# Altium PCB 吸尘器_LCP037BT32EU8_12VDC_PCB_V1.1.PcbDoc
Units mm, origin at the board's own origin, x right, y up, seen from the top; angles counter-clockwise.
Board outline 41.5 x 41.5 mm, 2 copper layers (Top Layer, Bottom Layer); 77 components, 42 nets, 206 pads, 122 vias.
Unrouted connection lines stored in the file: 7.
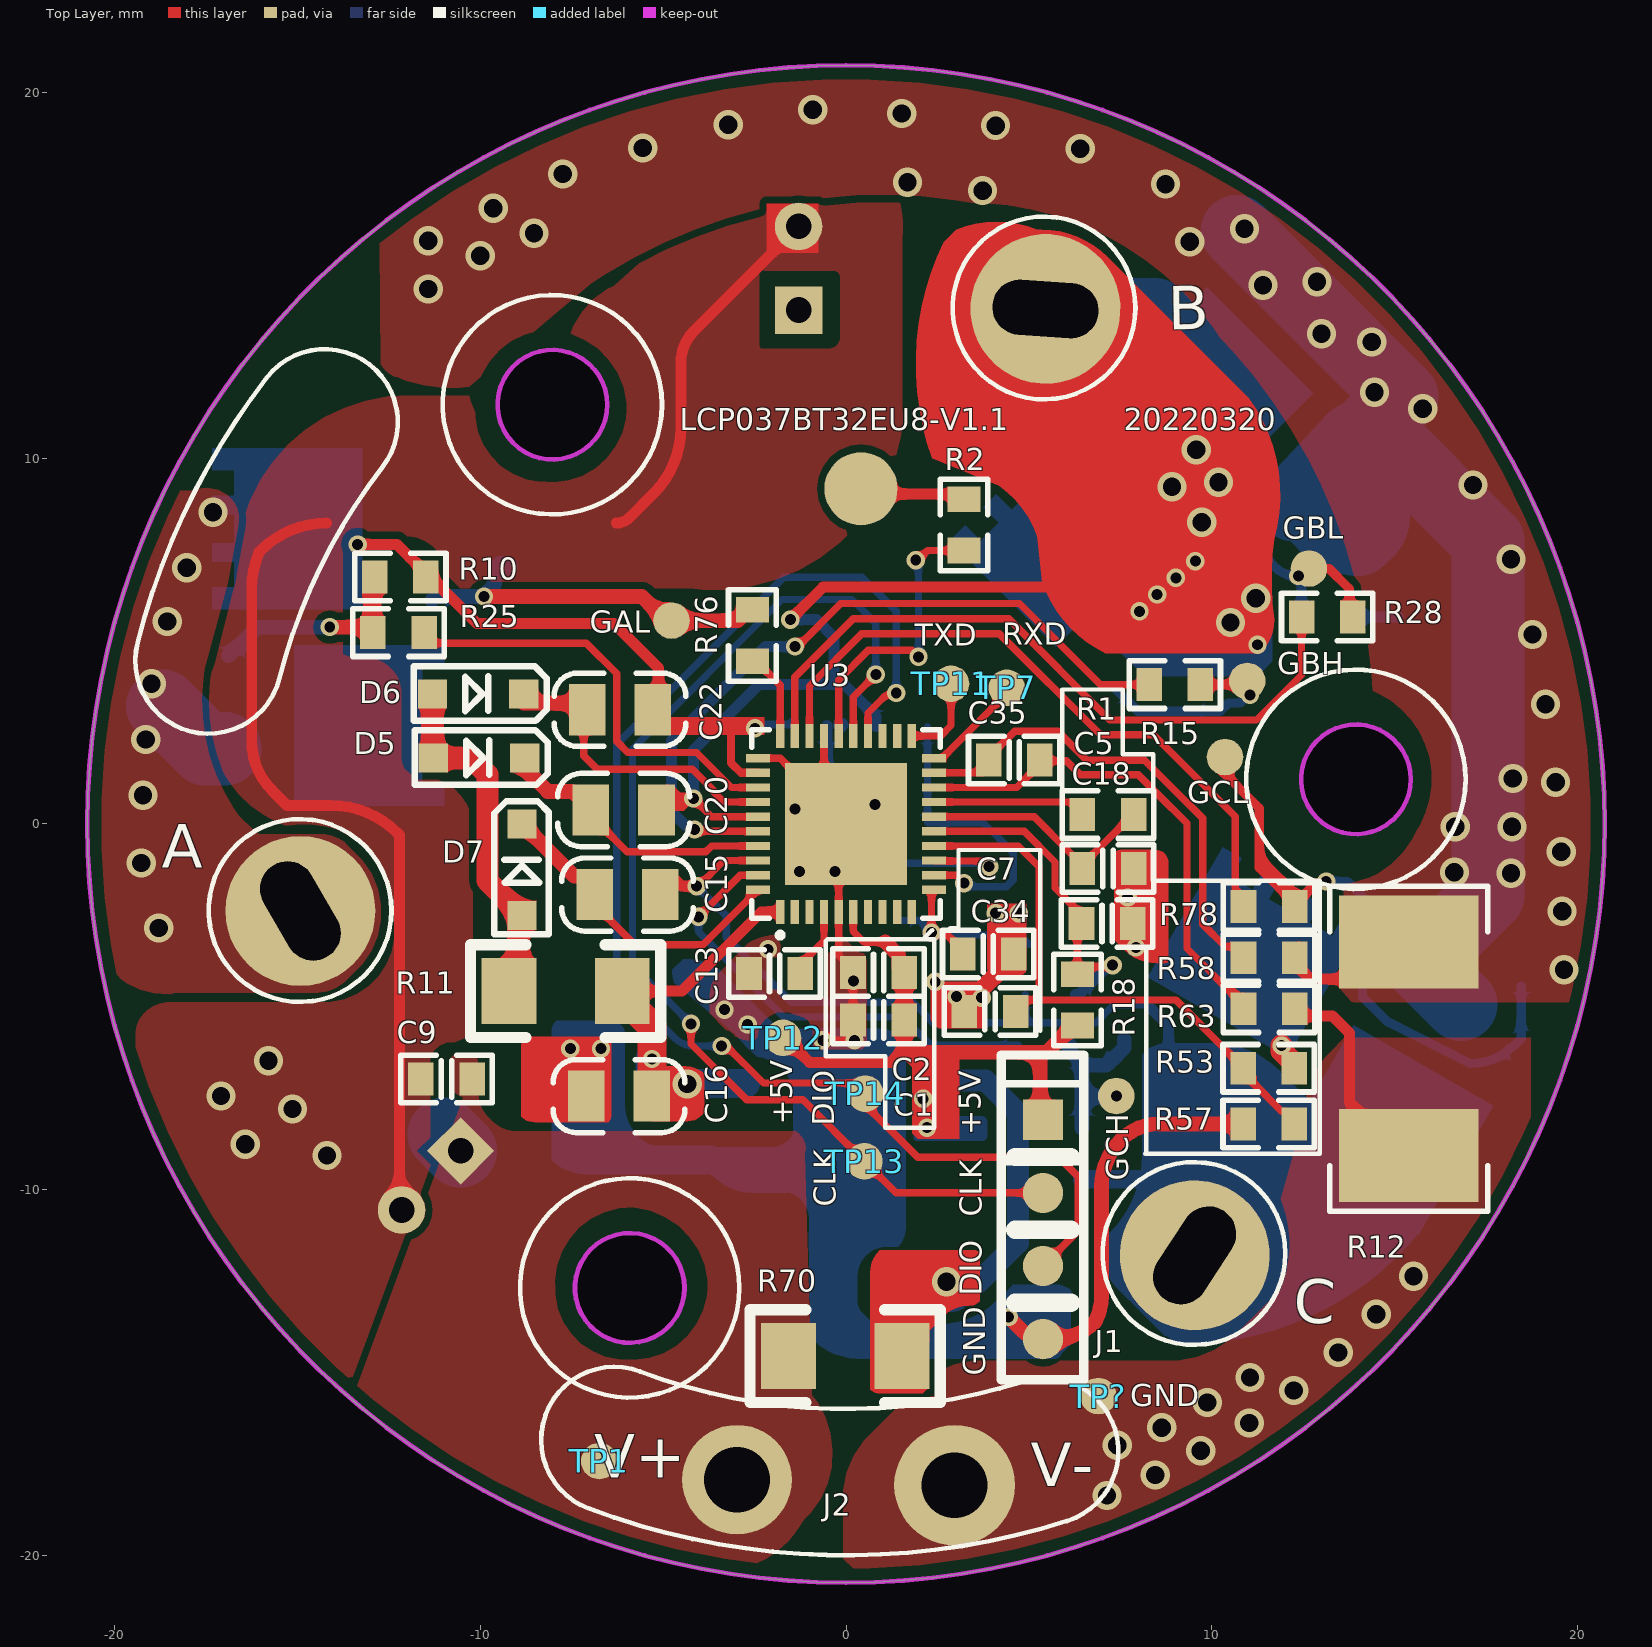
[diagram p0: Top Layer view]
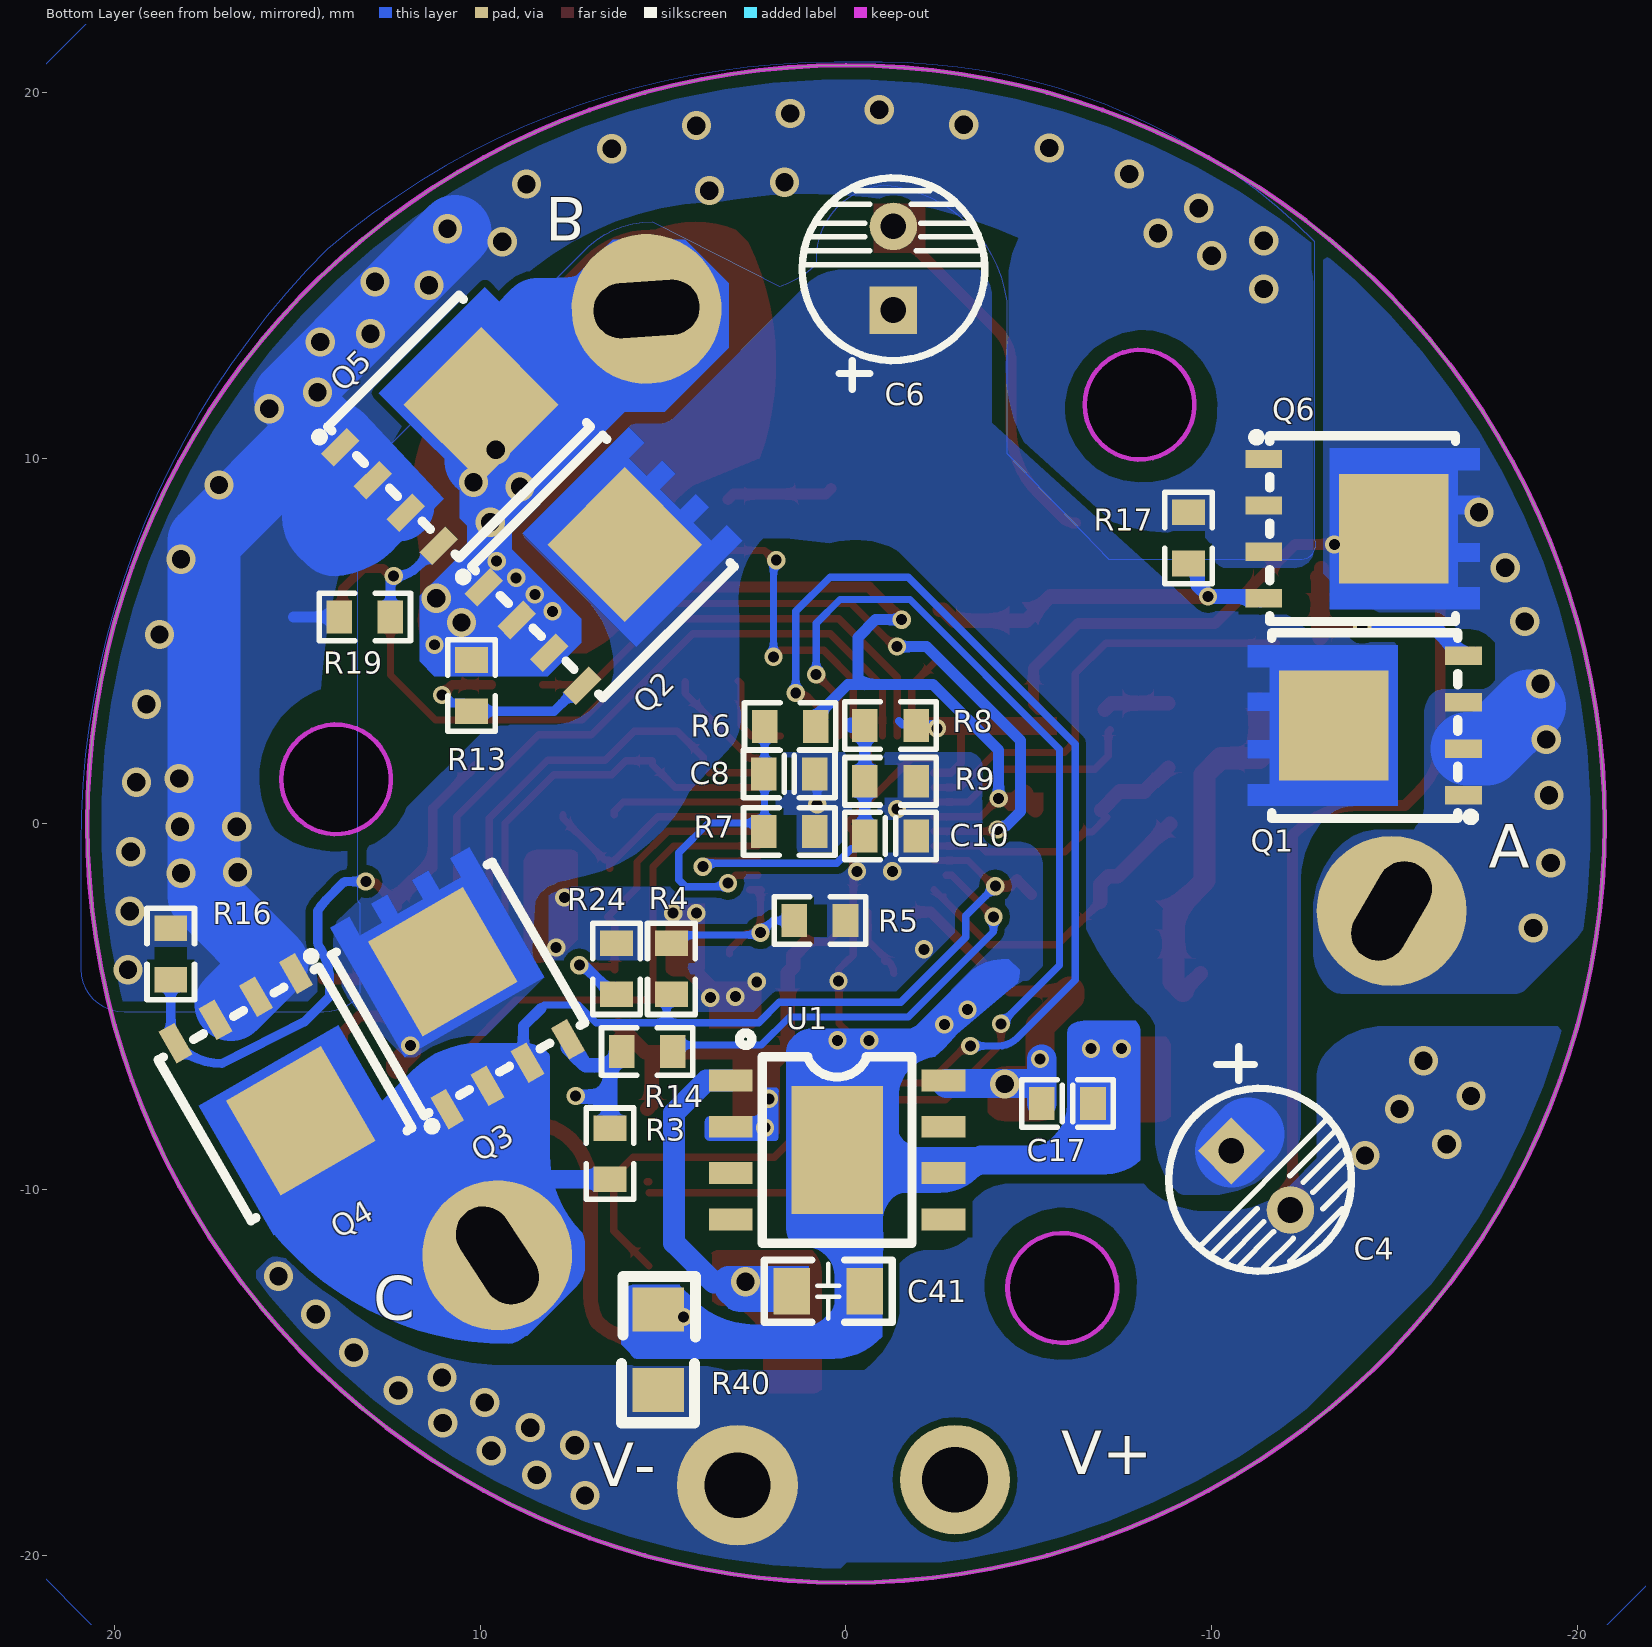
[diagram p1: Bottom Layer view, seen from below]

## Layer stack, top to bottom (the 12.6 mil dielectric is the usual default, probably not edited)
Top Solder: solder mask 0.0102, Solder Resist, Dk 3.5
Top Layer: signal copper 0.0356
Dielectric1: dielectric 0.32, FR-4, Dk 4.8
Bottom Layer: signal copper 0.0356
Bottom Solder: solder mask 0.0102, Solder Resist, Dk 3.5

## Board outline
-20.753,-0.001 ccw(c-0.003,-0.001) -0.003,-20.751 ccw(c-0.003,-0.001) 20.747,-0.001 ccw(c-0.003,-0.001) -0.003,20.749 ccw(c-0.003,-0.001)
cut-out: -7.418,-12.689 ccw(c-5.918,-12.689) -5.918,-14.189 ccw(c-5.918,-12.689) -4.418,-12.689 ccw(c-5.918,-12.689) -5.918,-11.189 ccw(c-5.918,-12.689)
cut-out: 12.444,1.221 ccw(c13.944,1.221) 13.944,-0.279 ccw(c13.944,1.221) 15.444,1.221 ccw(c13.944,1.221) 13.944,2.721 ccw(c13.944,1.221)
cut-out: -9.534,11.467 ccw(c-8.034,11.467) -8.034,9.967 ccw(c-8.034,11.467) -6.534,11.467 ccw(c-8.034,11.467) -8.034,12.967 ccw(c-8.034,11.467)

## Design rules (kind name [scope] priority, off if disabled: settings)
BoardOutlineClearance [All] p1: gap=0.381
Clearance [All] p1: gap=0.2
ComponentClearance [All] p1: gap=0 collisioncheckmode=3 verticalgap=0 showdistances=FALSE
HoleSize [All] p1: absolutevalues=TRUE maxlimit=4 minlimit=0.025 maxpercent=80.000 minpercent=20.000
MinimumSolderMaskSliver [All] p1: minsoldermaskwidth=0.18
PlaneConnect [All] p1: planeconnectstyle=Direct reliefexpansion=0.508 reliefentries=4 reliefconductorwidth=0.254 reliefairgap=0.254
PolygonConnect [All] p1: connectstyle=Direct reliefconductorwidth=0.254 reliefentries=4 polygonreliefangle="90 Angle" airgapwidth=0.254
RoutingVias [All] p1: holewidth=0.3 width=0.5 viastyle="Through Hole" minholewidth=0.2 minwidth=0.4 maxholewidth=0.3 maxwidth=0.5
SolderMaskExpansion [All] p1: expansion=0.102
Width [All] p1: maxlimit=5 minlimit=0.2 preferedwidth=0.254
26 further rules are at their usual default settings.

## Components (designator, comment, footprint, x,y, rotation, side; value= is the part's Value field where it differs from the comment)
A "Wire#18(BL)6cm" TP4MM#1 -10.825,-2.3 r270 top locked
B "Wire#18-(WT)6cm" TP4MM#2 0.85,14.075 r91 top locked
C "Wire#18(YE)6cm" TP4MM#3 15.925,-16.55 r177 top locked
C1 "106/25V" C0603X 0.889,-5.359 r180 top
C2 "0.1uF/50V" C0603X 0.889,-4.064 r0 top
C4 "100uF/35V" CDE5*7 -11.35,-9.75 r225 bottom
C5 "Cap" C0603X 7.163,-1.219 r0 top
C6 "100uF/35V" CDE5*7 -1.3,15.2 r90 bottom locked
C7 "332/50V" C0603X 3.886,-3.556 r0 top
C8 "332/50V" C0603X 1.549,1.372 r180 bottom
C9 "104/50V" C0603X -10.928,-6.977 r0 top
C10 "332/50V" C0603X -1.219,-0.33 r180 bottom
C13 "0.1uF/50V 0603" C0603X -1.956,-4.089 r180 top
C15 "10uF/25V 0805" C0805 -5.08,-1.93 r180 top
C16 "10uF/25V 0805" C0805 -7.112,-7.442 r0 top
C17 "0.1uF/50V 0603" C0603X -6.059,-7.645 r180 bottom
C18 "103/50V 0603" C0603X 7.137,-2.718 r0 top
C20 "10uF/25V 0805" C0805 -5.185,0.381 r180 top
C22 "10uF/25V 0805" C0805 -5.283,3.124 r180 top
C34 "104/50V" C0603X 3.937,-5.131 r0 top
C35 "101/50V" C0603X 4.597,1.753 r0 top
C41 "10uF/25V" 0805C 0.483,-12.776 r0 bottom
D5 "SD103AW" SOD323 -11.288,1.803 r0 top
D6 "SD103AW" SOD323 -11.314,3.556 r0 top
D7 "SD103AW" SOD323 -8.865,-2.5 r90 top
GAL "TestPoint" TP_1.0-A -4.775,5.563 r180 top (schematic designator TP8)
GBH "TestPoint" TP_1.0-A 10.973,3.912 r90 top (schematic designator TP5)
GBL "TestPoint" TP_1.0-A 12.66,6.985 r90 top (schematic designator TP9)
GCH "TestPoint" TP_1.0-A 7.391,-7.442 r90 top (schematic designator TP6)
GCL "TestPoint" TP_1.0-A 10.363,1.829 r90 top (schematic designator TP10)
J1 "CON4" SIP-4-TP 5.385,-8.09 r270 bottom locked
J2 "CON2" CON2-1.7MM -0.533,-18.11 r180 top
Q1 "1511" DNF5*6 -16.891,0.787 r90 bottom locked
Q2 "1511" DNF5*6 9.906,6.477 r225 bottom locked
Q3 "1511" DNF5*6 10.904,-7.798 r150 bottom locked
Q4 "1511" DNF5*6 15.039,-4.089 r330 bottom locked
Q5 "1511" DNF5*6 13.836,10.305 r225 bottom locked
Q6 "1511" DNF5*6 -11.43,9.982 r270 bottom locked
R1 "10K" R0603X 7.163,0.254 r0 top
R2 "1K" R0603X 3.226,8.179 r90 top
R3 "20K" R0603X 6.452,-9.017 r270 bottom
R4 "22K 1%" R0603X 4.775,-3.962 r90 bottom
R5 "5.1K 1%" R0603X 0.711,-2.642 r180 bottom
R6 "22K 1%" R0603X 1.524,2.667 r0 bottom
R7 "5.1K 1%" R0603X 1.549,-0.203 r180 bottom
R8 "22K 1%" R0603X -1.219,2.692 r0 bottom
R9 "5.1K 1%" R0603X -1.219,1.168 r180 bottom
R10 "20K" R0603X -12.192,6.756 r0 top
R11 "5.1R/1206" 1206/X -7.671,-4.572 r0 top
R12 "5mR/2512" 2512A 15.392,-3.353 r270 top
R13 "20K" R0603X 10.236,3.785 r90 bottom
R14 "51R 5% 0603" R0603X 5.436,-6.223 r180 bottom
R15 "51R 5% 0603" R0603X 8.992,3.81 r180 top
R16 "20K" R0603X 18.466,-3.556 r90 bottom
R17 "20K" R0603X -9.373,7.823 r90 bottom
R18 "5.1K 1% 0603" R0603X 6.325,-4.812 r90 top
R19 "20K" R0603X 13.157,5.664 r0 bottom
R24 "10K NTC B=4250" R0603X 6.274,-3.962 r270 bottom
R25 "51R 5% 0603" R0603X -12.243,5.232 r0 top
R28 "51R 5% 0603" R0603X 13.157,5.664 r180 top
R40 "0R 0805" R0805 5.131,-14.376 r270 bottom
R53 "100K 1% 0603" R0603X 11.557,-6.68 r0 top
R57 "10K 1% 0603" R0603X 11.557,-8.204 r0 top
R58 "68R 1% 0603" R0603X 11.568,-3.658 r0 top
R63 "68R 1% 0603" R0603X 11.568,-5.055 r0 top
R70 "20R 5% 1206" 1206/X -0.025,-14.554 r0 top
R76 "51R 5% 0603" R0603X -2.565,5.156 r270 top
R78 "51R 5% 0603" R0603X 11.568,-2.261 r180 top
TP1 "TestPoint" TP_1.0-A -6.75,-17.425 r90 top
TP7 "TestPoint" TP_1.0-A 4.394,3.727 r90 top
TP11 "TestPoint" TP_1.0-A 2.87,3.835 r90 top
TP12 "TestPoint" TP_1.0-A -1.725,-5.85 r90 top locked
TP13 "TestPoint" TP_1.0-A 0.5,-9.225 r90 top locked
TP14 "TestPoint" TP_1.0-A 0.525,-7.375 r90 top locked
TP? "TestPoint" TP_1.0-A 6.9,-15.648 r90 top locked
U1 "EG1205" ESOP-8 0.241,-8.915 r270 bottom locked
U3 "LCP037B32B" QFN-40-1 -0.503,-0.526 r0 top locked

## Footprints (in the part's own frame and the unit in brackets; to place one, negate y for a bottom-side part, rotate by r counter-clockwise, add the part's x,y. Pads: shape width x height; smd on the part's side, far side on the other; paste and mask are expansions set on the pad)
0805C [mm]
  rect 1x1.27 smd: 1(-1,0) 2(1,0)
  silkscreen extent -1.75,-0.85 1.75,0.85
1206/X [mm]
  rect 1.5x1.8 smd: 1(-1.55,0) 2(1.55,0)
  silkscreen extent -2.6,-1.27 2.6,1.27
2512A [mil]
  rect 100x150 smd: 1(-5,0) 2(225,0)
  silkscreen extent -65,-85 285,85, body extent -17,-66 243,66, height 33
C0603X [mm]
  rect 0.7x0.9 smd: 1(-0.7,0) 2(0.7,0)
  Top Layer pour cut-out: -0.2,0.45 -0.2,-0.45 0.2,-0.45 0.2,0.45
  silkscreen extent -1.25,-0.65 1.25,0.65
C0805 [mm]
  rect 1x1.4 smd: 1(0,0) 2(1.8,0)
  silkscreen extent -0.9,-1 2.7,1
CDE5*7 [mm]
  rect 1.3x1.3 hole 0.7: 1(-1.143,0)
  round 1.3 hole 0.7: 2(1.143,0)
  silkscreen extent -2.53,-2.5 2.47,2.5, body extent -2.5,-2.5 2.5,2.5, height 7
CON2-1.7MM [mm]
  round 3.3 hole 1.8: 1(-3.5,-0.025)
  round 3 hole 1.8: 2(2.45,-0.175)
DNF5*6 [mm]
  rect 0.5x1 smd: 1(0,0) 1(1.27,0) 1(2.54,0) 4(3.81,0)
  rect 3x3 smd: 5(1.905,3.55)
  Top Layer region: -0.295,1.8 -0.295,5.9 0.305,5.9 0.305,5.3 1.005,5.3 1.005,5.9 1.505,5.9 1.505,5.3 2.305,5.3 2.305,5.9 2.805,5.9 2.805,5.3 3.505,5.3 3.505,5.9 4.105,5.9 4.105,1.8
  silkscreen extent -0.69,-0.3 4.45,5.24
ESOP-8 [mm] "EG1205"
  rect 0.6x1.2 smd: 1(-1.905,-2.908) 2(-0.635,-2.908) 3(0.635,-2.908) 4(1.905,-2.908) 5(1.905,2.908) 6(0.635,2.908) 7(-0.635,2.908) 8(-1.905,2.908)
  rect 3.5x2.5 smd: 9(0,0)
  silkscreen extent -3.2,-2.67 2.55,2.05
QFN-40-1 [mm]
  rect 0.224x0.665 smd: 1(-1.3,-1.882) 2(-0.9,-1.882) 3(-0.5,-1.882) 4(-0.1,-1.882) 5(0.3,-1.882) 6(0.7,-1.882) 7(1.1,-1.882) 8(1.5,-1.882) 9(1.9,-1.882) 10(2.3,-1.882) 21(2.3,2.933) 22(1.9,2.933) 23(1.5,2.933) 24(1.1,2.933) 25(0.7,2.933) 26(0.3,2.933) 27(-0.1,2.933) 28(-0.5,2.933) 29(-0.9,2.933) 30(-1.3,2.933)
  rect 0.665x0.224 smd: 11(2.907,-1.275) 12(2.907,-0.875) 13(2.907,-0.475) 14(2.907,-0.075) 15(2.907,0.325) 16(2.907,0.725) 17(2.907,1.125) 18(2.907,1.525) 19(2.907,1.925) 20(2.907,2.325) 31(-1.908,2.325) 32(-1.908,1.925) 33(-1.908,1.525) 34(-1.908,1.125) 35(-1.908,0.725) 36(-1.908,0.325) 37(-1.908,-0.075) 38(-1.908,-0.475) 39(-1.908,-0.875) 40(-1.908,-1.275)
  rect 3.325x3.325 smd: 41(0.5,0.525)
  silkscreen extent -2.08,-2.59 3.08,3.1
R0603X [mm]
  rect 0.7x0.9 smd: 1(-0.7,0) 2(0.7,0)
  Top Layer pour cut-out: -0.2,0.45 -0.2,-0.45 0.2,-0.45 0.2,0.45
  silkscreen extent -1.25,-0.65 1.25,0.65
R0805 [mm]
  rect 1.2x1.4 smd: 1(-1.1,0) 2(1.1,0)
  silkscreen extent -2,-1.01 2,1.02
SIP-4-TP [mm] "贴片针座"
  rect 1.1x1.1 smd far side: 1(0,0)
  round 1.1 smd far side: 2(2,0) 3(4,0) 4(6,0)
SOD323 [mm]
  rect 0.8x0.8 smd: 1(0,0) 2(2.5,0)
  silkscreen extent -0.51,-0.74 3.12,0.76, body extent -0.06,-0.64 2.54,0.66, height 1
TP4MM#1 [mm] "LX-椭圆插件"
  round 4.1 hole 1.5 slot 2.9 at 30 deg: 1(0.079,-4.1)
TP4MM#2 [mm] "LX-椭圆插件"
  round 4.1 hole 1.5 slot 2.9 at 85 deg: 1(-0.069,-4.602)
TP4MM#3 [mm] "LX-椭圆插件"
  round 4.1 hole 1.5 slot 2.9 at 60 deg: 1(6.632,-4.409)
TP_1.0-A [mm] "无丝印"
  round 1 smd: 1(0,0)

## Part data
A B C: library part Wire
C1 C9 C15 C16 C20 C22 C34 C35 C41: library part CAP, "Capacitor"
C2 C7 C8 C10 C13 C17 C18: library part CAP
C4 C6: library part ELECTRO1, "Electrolytic Capacitor"
C5: "Capacitor"
D5 D6 D7: library part DIODE, "SBD"
GAL GBH GBL GCH GCL TP1 TP7 TP11 TP12 TP13 TP14 TP?: "Testpoint"
J2: "Connector"
Q1 Q2 Q3 Q4 Q5 Q6: library part RJK0822, "NMOS"
R1 R2: library part R
R3 R4 R5 R6 R7 R8 R9 R10 R11 R13 R16 R17 R19: library part RES2
R12 R14 R15 R25 R28 R76 R78: library part Res2, "Resistor"
R18 R40 R53 R57 R58 R63 R70: library part RES
R24: library part RES-V
U3: library part LCP037B32A

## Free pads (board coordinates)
  round 2 smd: 10(0.406,9.169)

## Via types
v1: diameter 0.8, hole 0.5, Top Layer to Bottom Layer, tented both sides, 69 vias
v2: diameter 0.5, hole 0.3, Top Layer to Bottom Layer, tented both sides, 53 vias

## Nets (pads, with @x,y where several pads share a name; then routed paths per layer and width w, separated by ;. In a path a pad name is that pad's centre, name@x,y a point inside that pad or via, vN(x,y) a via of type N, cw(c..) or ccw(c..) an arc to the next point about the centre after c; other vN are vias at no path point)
+5V: C1.1 C2.2 J1.1 R18.1 TP12.1 U1.2 U3.6 | length 18.1
  Top Layer w0.2: U3.6 0.197,-2.896 ccw(c0.304,-2.896) 0.229,-2.972 0.483,-3.226 1.067,-3.226
  Top Layer w0.3: TP12.1 -1.668,-5.85 -1,-6.518 1.229,-6.518 1.499,-6.248
  Top Layer w0.4: 1.067,-3.226 1.439,-3.598 1.439,-3.914 C2.2 C1.1 1.589,-6.158 1.499,-6.248 2.057,-6.248 ; v2(2.21,-8.306) 2.21,-6.401 2.057,-6.248 ; J1.1@5.436,-7.786 5.309,-7.659 5.309,-6.248 ; R18.1@6.225,-5.512 5.488,-6.248 5.309,-6.248 ; 2.057,-6.248 5.309,-6.248
  Bottom Layer w0.3: v2(2.21,-8.306) 2.222,-8.293 3.137,-8.293 U1.2
  other v2: 2.108,-7.518
+12V: C16.2 C17.1 R11.2 U1.8 U3.1 | length 12.2
  Top Layer w0.3: R11.2 -4.484,-4.572 -2.32,-2.408 U3.1@-1.865,-2.408
  Top Layer w0.8: R11.2 -6.121,-4.722 -5.309,-5.534 v2(-5.309,-6.426) ; C16.2 v2@-5.312,-6.426
  Bottom Layer w0.8: C17.1 -5.359,-7.01 ; v2@-5.359,-6.426 -5.359,-7.01 ; U1.8@-2.755,-7.098 -5.271,-7.098 -5.359,-7.01
  other v1: -4.343,-7.112
DCIN: C4.1 C6.1 C9.2 J2.2 Q1.5 Q2.5 Q3.5 R53.2 R70.1 TP1.1 | length 1.4
  Top Layer w0.6: v2(11.913,-6.064) 11.913,-6.21 12.282,-6.58 R53.2@12.282,-6.68
  Bottom Layer w2: C4.1@-10.998,-8.485 C4.1
GAH: Q1.4 R10.1 R25.1 | length 7.6
  Top Layer w0.4: v2(-14.122,5.385) -13.235,5.385 R25.1@-13.159,5.461 ; R25.1@-13.006,5.232 R10.1@-13.006,6.998 ; R25.1@-12.968,5.08 -13.006,5.118 -12.917,5.207 -12.917,6.731 R10.1
  Bottom Layer w0.4: Q1.4 -16.104,5.385 v2(-14.122,5.385)
GAL: GAL.1 Q6.4 R17.1 R76.1 | length 10.5
  Top Layer w0.4: v2(-9.906,6.223) -5.588,6.223 -4.928,5.563 GAL.1 -2.959,5.563 -2.665,5.856 R76.1
  Bottom Layer w0.4: Q6.4@-11.328,6.121 -11.227,6.223 v2(-9.906,6.223) -9.906,6.25 -9.623,6.533 -9.623,6.973 -9.473,7.123 R17.1 ; R17.1@-9.276,6.993 R17.1@-9.169,7.072
GBH: GBH.1 Q2.4 R13.1 R15.1 | length 5.8
  Top Layer w0.254: R15.1 10.77,3.81 v2(11.049,3.531)
  Bottom Layer w0.254: Q2.4 7.283,3.783 7.981,3.085 R13.1 10.459,3.308 10.777,3.308 11,3.531 v2(11.049,3.531)
GBL: GBL.1 Q5.4 R19.1 R28.1 | length 5.3
  Top Layer w0.254: GBL.1@12.344,6.843 ccw(c12.431,6.843) v2(12.37,6.782) ccw(c12.431,6.843) 12.431,6.756 GBL.1 13.208,6.985 13.749,6.444 cw(c13.705,6.401) 13.767,6.401 13.767,5.882 ccw(c14.075,5.882) R28.1
  Bottom Layer w0.254: Q5.4 11.711,7.042 ccw(c12.392,7.723) 12.392,6.759 cw(c12.235,6.602) 12.457,6.602 R19.1
GCH: GCH.1 Q3.4 R3.1 R14.1 | length 5
  Bottom Layer w0.4: R14.1@6.11,-6.223 R14.1@6.11,-6.045 ; R14.1 6.452,-6.539 R14.1@6.452,-6.604 ; R14.1@6.364,-6.604 R14.1@6.452,-6.604 ; R3.1 6.452,-7.461 ; v2(7.391,-7.442) 7.372,-7.461 6.452,-7.461 ; Q3.4 7.605,-6.117 7.118,-6.604 R14.1@6.452,-6.604 ; 6.452,-7.461 R14.1@6.452,-6.604
GCL: GCL.1 Q4.4 R16.1 R78.1 | length 17.9
  Top Layer w0.254: GCL.1@10.135,1.6 11.303,0.432 11.303,-0.927 ; R78.1 12.268,-2.161 11.303,-1.195 11.303,-0.927 ; v2(13.132,-1.575) 13.085,-1.622 12.856,-1.622 12.427,-2.051 11.303,-0.927
  Bottom Layer w0.254: v2(13.132,-1.575) 13.665,-1.575 cw(c13.665,-1.697) 13.752,-1.611 14.224,-2.083 cw(c13.246,-3.061) 14.448,-2.376 14.448,-3.196 cw(c14.118,-3.196) 14.423,-3.321 cw(c14.118,-3.196) 14.361,-3.418 ccw(c15.852,-4.295) 14.122,-4.295 14.122,-4.724 14.808,-5.41 17.069,-6.553 ccw(c17.069,-4.836) 18.283,-6.05 Q4.4 18.466,-5.867 R16.1@18.466,-4.434
GND: C1.2 C2.1 C5.2 C7.2 C8.2 C10.2 C13.2 C16.1 C17.2 C18.2 C34.1 C41.1 J1.4 R5.2 R7.2 R9.2 R24.1 R40.1 R57.1 U1.6 U1.9 U3.5 U3.27 U3.31 U3.41 | length 42.9
  Top Layer w0.2: U3.31 -1.803,1.799 U3.41@-0.603,0.599 ; U3.27 U3.41@-0.603,0.599 ; v2@-0.515,-5.773 -0.37,-5.918 v2(0.229,-5.918) ; C1.2@-0.061,-5.709 0.189,-5.459 C1.2 C2.1 0.203,-4.078 v2(0.203,-4.293) 0.203,-3.978 -0.061,-3.714 -0.086,-3.714 -0.203,-3.597 U3.5 -0.203,-0.201 U3.41 U3.41@-0.603,0.599 ; C34.1 3.237,-5.031 v2@3.613,-4.655 ; C7.2@4.336,-3.932 4.336,-3.806 C7.2 4.586,-3.353 C7.2@4.724,-3.215
  Top Layer w0.3: C5.2@7.888,-1.041 7.901,-1.054 7.901,-2.629 7.919,-2.647 7.919,-3.373 v2(7.925,-3.378)
  Top Layer w0.4: v2@3.613,-4.655 C7.2@4.336,-3.932 ; v2(4.445,-13.487) 4.81,-13.852 ccw(c5.385,-13.277) J1.4 5.661,-14.09 ccw(c5.661,-12.466) 6.227,-13.988 ccw(c5.661,-12.466) 6.81,-13.614 ccw(c5.448,-12.902) 6.985,-12.902 6.985,-9.924 cw(c8.806,-9.924) 7.518,-8.636 cw(c8.561,-9.678) 8.561,-8.204 R57.1
  Bottom Layer w0.2: v2(0.787,0.533) 0.787,1.23 0.889,1.332 C8.2
  Bottom Layer w0.5: C17.2 -6.759,-7.745 -6.709,-7.795 -6.659,-7.845 -6.659,-8.403 -6.02,-9.042 -3.683,-9.042 -3.175,-9.55 U1.6
  Bottom Layer w0.6: C17.2 -6.709,-7.695 -6.709,-7.795 -6.709,-8.353 -6.659,-8.403
  Bottom Layer w1: U1.6 U1.9@-0.394,-9.55 ; C41.1@-0.382,-12.911 -0.517,-12.911 C41.1 -0.517,-10.174 -0.394,-10.051 U1.9@-0.394,-9.55 ; U1.9 U1.9@-0.394,-9.55 ; v2(4.445,-13.487) R40.1
  other v2: -7.544,-6.147 -6.706,-6.147 -0.635,-5.918 -2.692,-5.486 -3.327,-5.08 3.708,-4.75 3.023,-4.724 2.438,-4.318 -2.134,-3.429 4.089,-2.438 4.724,-2.438 7.702,-2.012 -1.27,-1.295 -0.305,-1.295 -1.397,0.406
IN: C41.2 R70.2 U1.1 | length 12.5
  Top Layer w0.6: R70.2 1.975,-14.104 1.975,-12.707 2.134,-12.548 3.277,-12.548
  Bottom Layer w0.6: C41.2@1.483,-12.548 3.607,-12.548 4.699,-11.455 4.699,-7.899 3.81,-7.01 U1.1
  other v1: 2.743,-12.522
ISENCE: Q4.1 Q5.1 Q6.1 R12.1 R16.2 R17.2 R19.2 R58.2 | length 33.1
  Top Layer w0.3: R58.2@12.384,-3.353 12.384,-3.926 12.7,-4.242 R12.1@14.3,-4.242
  Bottom Layer w0.3: R19.2 15.113,5.664 ; 13.857,7.152 13.97,7.264
  Bottom Layer w2: v1@10.689,16.2 12.467,14.423 15.197,11.692 14.14,10.635 14.14,10.61 ; 12.256,8.725 14.14,10.61 ; 16.816,-4.936 15.693,-3.814 17.412,-2.095 17.551,-1.956 17.551,-0.076 17.551,7.74 14.682,10.61 14.14,10.61
  other v1: 19.634,-3.988 19.583,-2.388 18.186,-1.346 16.637,-1.321 19.558,-0.762 16.662,-0.076 18.212,-0.076 19.406,1.143 18.237,1.245 19.126,3.277 18.771,5.182 18.186,7.239 17.145,9.271 15.773,11.354 14.453,11.811 14.376,13.183 13.005,13.411 -11.43,14.63 11.405,14.732 12.878,14.834 -10.008,15.545 9.398,15.926 -11.43,15.951 -8.534,16.154 10.897,16.281 -9.652,16.84 3.734,17.323 8.738,17.501 1.676,17.551 -7.747,17.78 6.401,18.466 -5.563,18.491 4.089,19.101 -3.226,19.126 1.524,19.431 -0.914,19.533
MosTemp: C18.1 R18.2 R24.2 U3.15 | length 9.4
  Top Layer w0.2: U3.15 4.874,-0.201 5.715,-1.041 5.715,-1.743 6.514,-2.542 6.325,-2.731 6.325,-3.993 6.415,-3.903 7.248,-3.903 v2(7.29,-3.861)
  Bottom Layer w0.2: v2@7.232,-3.918 v2(7.29,-3.861)
  Bottom Layer w0.3: R24.2 6.374,-4.662 7.137,-3.899 7.213,-3.899 v2@7.232,-3.918
MOTOR_A: A.1 C22.1 Q1.1 Q6.5 R8.1 R10.2 U3.32 | length 16.9
  Top Layer w0.22: v2(-2.489,2.616) -3.15,2.616 -3.15,1.672 -2.879,1.401 -2.412,1.401 U3.32
  Top Layer w0.3: v2(-13.36,7.645) -12.281,7.645 -11.492,6.856 R10.2 ; R10.2@-11.644,7.036 -10.095,5.486 -6.35,5.486 -5.131,4.267 -5.131,3.277 C22.1
  Bottom Layer w0.22: v2(-2.489,2.616) -2.413,2.616 -2.312,2.718 -1.549,2.718 -1.449,2.818
  Bottom Layer w2: -18.693,3.229 -17.521,2.057 Q1.1@-16.993,2.057
  other v1: -18.796,-2.845 -19.279,-1.067 -19.228,0.787 -19.152,2.311 -18.999,3.835 -18.567,5.537 -18.034,7.01 -17.318,8.525
MOTOR_B: B.1 C20.1 Q2.1 Q5.5 R6.1 R13.2 U3.35 | length 34.7
  Top Layer w0.2: C20.1@-4.733,0.881 ccw(c-4.293,1.322) -4.293,0.699 v2(-4.178,0.699) -3.679,0.199 U3.35 ; 6.219,6.486 7.019,6.486 v1@10.135,9.601
  Top Layer w0.3: v2(-1.524,5.588) -0.626,6.486 6.219,6.486
  Top Layer w0.4: C20.1 -4.931,0.635 -4.931,0.835 C20.1@-4.885,0.881
  Bottom Layer w0.3: v2(-4.178,0.699) -4.178,2.019 -2.388,3.81 -0.506,3.81 ; v2(-1.524,5.588) -0.813,5.588 -0.33,5.105 -0.33,3.986 -0.506,3.81 ; R6.1 0.824,2.935 -0.051,3.81 -0.506,3.81
  Bottom Layer w2: B.1 5.609,13.93 8.438,13.93 10.426,11.942 Q5.5@10.731,11.942 ; Q5.5@9.978,9.927 Q5.5
  other v1: 10.516,5.512 11.201,6.172 9.728,8.255 8.915,9.22 10.185,9.347 9.576,10.236
  other v2: 11.252,4.902 8.026,5.817 8.509,6.274 9.017,6.731 9.55,7.188
MOTOR_C: C15.1 C.1 Q3.1 Q4.5 R3.2 R4.1 U3.38 | length 36.1
  Top Layer w0.2: v2(-4.086,-1.702) -4.039,-1.702 -3.337,-1.001 U3.38
  Top Layer w0.3: C15.1 -4.674,-1.524 -4.496,-1.702 v2(-4.086,-1.702)
  Bottom Layer w0.2: v2(-4.086,-1.702) -3.277,-2.511 -3.277,-3.099 -1.499,-4.877 1.829,-4.877 2.388,-5.436 4.902,-5.436 ; R4.1@4.902,-4.662 4.902,-5.436 ; 8.344,-5.042 8.255,-4.953 7.315,-4.953 6.833,-5.436 4.902,-5.436 ; Q3.1@8.705,-6.528 8.721,-6.544 9.186,-6.544 Q3.1@9.804,-7.163
  Bottom Layer w0.3: 8.344,-5.042 8.822,-5.52 8.822,-6.411 Q3.1@8.705,-6.528
  Bottom Layer w0.5: R3.2 8.469,-9.717 9.042,-9.144 ; 8.595,-8.814 8.839,-8.814
  Bottom Layer w2: C.1 9.935,-11.398 11.632,-11.398 13.154,-9.877 ; Q3.1@9.804,-7.163 12.519,-9.877 13.154,-9.877 ; Q4.5 13.154,-9.877
NetC15_2: C15.2 D7.2 U3.40 | length 8.7
  Top Layer w0.2: C15.2@-6.956,-2.13 -5.785,-3.302 -3.912,-3.302 U3.40
  Top Layer w0.4: D7.2 -7.434,-1.43 -7.18,-1.43 -6.956,-1.654 C15.2@-6.956,-2.13
NetC20_2: C20.2 D5.2 U3.37 | length 7.5
  Top Layer w0.2: C20.2@-7.134,0.181 -6.734,-0.219 -6.534,-0.219 -5.991,-0.762 -3.835,-0.762 -3.674,-0.601 U3.37
  Top Layer w0.4: D5.2@-8.814,1.537 -8.166,0.889 -7.493,0.889 C20.2
NetC22_2: C22.2 D6.2 U3.34 | length 7.8
  Top Layer w0.2: C22.2@-7.227,2.574 -7.177,2.524 -7.177,1.868 -6.807,1.499 -4.201,1.499 -3.628,0.926 -3.628,0.885 -3.343,0.599 U3.34
  Top Layer w0.4: D6.2@-8.814,3.302 -7.261,3.302 C22.2
NetD5_1: D5.1 D6.1 D7.1 R11.1 | length 10.2
  Top Layer w0.4: R11.1@-9.703,-4.09 R11.1
  Top Layer w0.6: D5.1@-11.314,1.803 D6.1@-11.314,3.302 ; D5.1 -10.257,1.803 -9.813,1.359 -9.813,-1.551 -8.965,-2.4 -8.965,-4.316 R11.1
NetR2_2: pad.10 R2.2 | length 2.9
  Top Layer w0.3: pad.10 0.552,9.024 3.081,9.024 R2.2
NetR14_2: R14.2 U3.39 | length 12.4
  Top Layer w0.2: v2(-4.039,-2.54) -2.899,-1.401 -2.743,-1.401
  Bottom Layer w0.2: v2(-4.039,-2.54) -4.039,-2.946 -1.708,-5.277 1.543,-5.277 2.311,-6.045 R14.2@4.71,-6.045 ; R14.2@4.607,-6.148 4.713,-6.254 R14.2@4.714,-6.254
NetR15_2: R15.2 U3.36 | length 20.1
  Top Layer w0.2: v2(-4.149,-0.152) -4.101,-0.201 U3.36 ; v2(-1.397,4.851) -1.321,4.851 -0.144,6.028 4.742,6.028 6.96,3.81 R15.2
  Bottom Layer w0.3: v2(-4.149,-0.152) -4.203,-0.152 -4.303,-0.052 -4.38,-0.052 -4.778,0.346 -4.778,2.283 -2.21,4.851 v2(-1.397,4.851)
NetR25_2: R25.2 U3.33 | length 12.1
  Top Layer w0.2: R25.2@-11.771,4.946 -7.105,4.946 -6.274,4.115 -6.274,2.261 -5.969,1.956 -4.089,1.956 -3.133,0.999 U3.33
NetR28_2: R28.2 U3.29 | length 19.4
  Top Layer w0.2: U3.29 -1.403,4.012 0.199,5.613 4.445,5.613 7.214,2.845 11.227,2.845 12.457,4.075 R28.2
NetR76_2: R76.2 U3.30 | length 2.4
  Top Layer w0.2: R76.2 -2.465,4.456 -1.803,3.793 U3.30
NetR78_2: R78.2 U3.28 | length 18
  Top Layer w0.2: U3.28 -1.003,3.773 0.432,5.207 4.191,5.207 6.96,2.438 8.407,2.438 10.643,0.203 10.643,-1.767 R78.2@10.857,-1.981
NRES: C13.1 U3.4 | length 2
  Top Layer w0.2: C13.1@-1.307,-4.089 cw(c-0.843,-4.089) -1.292,-3.975 cw(c-0.843,-4.089) -1.171,-3.761 -1.079,-3.761 -1.057,-3.739 -1.057,-3.647 -0.659,-3.25 ; -0.603,-3.25 U3.4
OPA0_OUT: R1.1 U3.17 | length 4.1
  Top Layer w0.2: U3.17 6.086,0.599 6.336,0.349 R1.1@6.336,0.254
OPA0_OUT_LPF: C5.1 R1.2 U3.16 | length 6.5
  Top Layer w0.2: U3.16 5.144,0.199 6.08,-0.737 6.463,-1.119 C5.1 ; C5.1@6.488,-0.987 6.595,-0.987 7.736,0.154 R1.2@7.736,0.254
OPA0N: C35.2 R63.1 U3.18 | length 14.5
  Top Layer w0.2: U3.18 4.67,0.999 5.297,1.627 5.297,1.727 6.02,1.727 6.4,1.347 7.994,1.347 8.513,0.828 ; 8.513,0.828 9.322,0.019 9.322,-3.408 10.868,-4.955 R63.1 ; 10.394,-4.408 10.413,-4.408 R63.1@10.959,-4.953
OPA0P: C35.1 R58.1 U3.19 | length 13
  Top Layer w0.2: U3.19 C35.1@3.736,1.399 ; C35.1@3.897,1.727 3.897,1.827 4.61,2.54 5.791,2.54 6.584,1.747 8.16,1.747 8.913,0.994 9.754,0.152 9.754,-2.743 10.363,-3.353 R58.1@10.984,-3.353
PGND: C4.2 C6.2 C9.1 J2.1 R12.2 R40.2 R63.2 TP?.1 | length 39.1
  Top Layer w0.3: -14.208,8.23 ccw(c-14.208,5.69) -16.005,7.486 -16.052,7.438 ccw(c-13.716,6.441) -16.256,6.441 -16.256,2.261 ccw(c-14.355,2.261) -15.699,0.916 -15.291,0.508 -14.082,0.508 cw(c-14.082,-2.032) -12.286,-0.236 -12.217,-0.305 -12.217,-10.416 ccw(c-12.016,-10.416) C4.2 ; -6.286,8.23 ccw(c-6.286,8.75) -5.918,8.382 -5.265,9.035 ccw(c-7.061,10.831) -4.521,10.831 -4.521,12.598 cw(c-3.258,12.598) -4.151,13.492 C6.2 ccw(c-1.3,16.074) C6.2@-1.49,16.264 ; R63.2@12.409,-4.953 12.409,-5.053 12.609,-5.253 13.305,-5.253 13.764,-5.713 13.764,-7.618 14.884,-8.738 R12.2@15.519,-8.738
  other v1: 7.137,-18.364 8.458,-17.805 9.703,-17.145 7.417,-16.993 8.636,-16.51 11.024,-16.383 9.881,-15.824 12.243,-15.494 11.049,-15.138 13.462,-14.453 14.503,-13.411 15.519,-12.37 -14.199,-9.068 -16.434,-8.763 -15.138,-7.798 -17.094,-7.442 -15.799,-6.477
PWM: R2.1 U3.26 | length 8.2
  Top Layer w0.2: U3.26 -0.203,3.938 0.61,4.75 1.803,4.75 v2(1.981,4.572) ; v2@1.961,7.214 2.226,7.479 R2.1
  Bottom Layer w0.2: v2(1.905,7.214) 1.981,7.137 v2(1.981,4.572)
RXD: TP7.1 U3.20 | length 3
  Top Layer w0.2: U3.20 2.625,1.799 4.394,3.568 TP7.1@4.394,3.886
SWCLK: J1.2 TP13.1 U3.25 | length 32
  Top Layer w0.2: v2(-4.242,-5.467) -4.242,-6.02 -2.718,-7.544 -1.181,-7.544 TP13.1 1.365,-10.09 J1.2 ; U3.25 0.197,3.474 v2(0.813,4.089) ; J1.2@5.385,-9.786 J1.2@5.436,-9.786
  Bottom Layer w0.2: v2(-4.242,-5.467) -5.842,-3.867 -5.842,2.048 -1.752,6.138 0.161,6.138 0.813,5.486 v2(0.813,4.089)
SWDIO: J1.3 TP14.1 U3.24 | length 38.1
  Top Layer w0.2: v2(-3.404,-6.071) -3.277,-6.071 -2.261,-7.087 0.237,-7.087 TP14.1 0.525,-7.688 1.956,-9.119 5.817,-9.119 6.35,-9.652 6.35,-11.125 J1.3 ; U3.24 0.597,3.036 0.981,3.42 cw(c1.372,3.03) v2(1.372,3.581)
  Bottom Layer w0.2: v2(-3.404,-6.071) -4.165,-6.071 cw(c-4.165,-5.333) -4.686,-5.855 -6.274,-4.267 -6.274,2.182 -1.705,6.751 0.437,6.751 1.372,5.817 v2(1.372,3.581)
TXD: TP11.1 U3.21 | length 2.4
  Top Layer w0.2: U3.21 2.585,2.407 2.87,2.692 TP11.1 TP11.1@2.946,3.912
VMA: C10.1 R8.2 R9.1 U3.13 | length 9.5
  Top Layer w0.2: U3.13 2.417,-1.013 3.005,-1.013 3.006,-1.011 3.755,-1.011 v2(3.912,-1.168)
  Bottom Layer w0.2: C10.1 -0.519,-0.43 -0.269,-0.68 -0.142,-0.68 0.248,-1.07 3.814,-1.07 v2(3.912,-1.168)
  Bottom Layer w0.3: C10.1 R9.1 R8.2
  Bottom Layer w0.4: -0.164,2.692 -0.138,2.718
VMB: C8.1 R6.2 R7.1 U3.12 | length 8.4
  Top Layer w0.2: U3.12 3.021,-1.401 3.226,-1.605 v2(3.226,-1.62)
  Bottom Layer w0.2: R6.2 2.224,0.051 2.249,0.025 3.759,0.025 4.572,-0.787 4.572,-1.524 4.378,-1.718 3.405,-1.718 3.307,-1.62 v2(3.226,-1.62)
VMC: C7.1 R4.2 R5.1 U3.11 | length 6.5
  Top Layer w0.2: U3.11@2.639,-1.801 U3.11 2.323,-1.801 2.311,-1.813 2.337,-1.838 v2(2.337,-2.972) 2.369,-3.004 2.734,-3.004 3.186,-3.456 C7.1
  Bottom Layer w0.2: R5.1 2.007,-2.642 v2(2.337,-2.972) 2.418,-2.972 2.484,-3.038 4.754,-3.038 R4.2@5.004,-3.288
VolDect: C34.2 R53.1 R57.2 U3.14 | length 15.9
  Top Layer w0.2: U3.14 4.709,-0.601 5.274,-1.166 5.274,-4.719 5.182,-4.812 ; C34.2@4.802,-4.812 5.182,-4.812 ; R57.2 12.257,-8.104 12.007,-7.854 11.907,-7.854 11.132,-7.08 11.132,-6.93 10.882,-6.68 10.882,-6.58 10.632,-6.33 10.532,-6.33 9.014,-4.812 5.182,-4.812
pads on no net: U1.3 U1.4 U1.5 U1.7 U3.2 U3.3 U3.7 U3.8 U3.9 U3.10 U3.22 U3.23

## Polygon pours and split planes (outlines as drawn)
GND on Top Layer "GND_L01_P104" (solid, remove dead copper, pour order 104): -3.734,-4.75 cw(c-2.63,-4.75) -3.411,-3.969 -2.866,-3.425 cw(c-1.956,-4.336) -1.956,-3.048 cw(c-2.438,-3.531) -1.756,-3.531 -1.756,-4.562 ccw(c-1.396,-4.387) -1.526,-4.765 -0.676,-4.765 ccw(c-1.014,-4.336) -0.584,-4.674 -0.584,-3.977 cw(c0.37,-3.977) -0.305,-3.302 cw(c0.087,-3.302) -0.19,-3.025 -0.103,-2.938 0.428,-3.468 cw(c0.111,-3.784) 0.559,-3.785 0.559,-5.902 cw(c0.212,-5.902) 0.457,-6.147 cw(c0.335,-6.024) 0.335,-6.198 -0.711,-6.198 cw(c-0.711,-6.014) -0.841,-6.144 -0.914,-6.071 -0.914,-5.691 ccw(c-1.348,-5.691) -1.041,-5.385 ccw(c-1.409,-5.752) -1.409,-5.232 -2.057,-5.232 cw(c-2.793,-5.233) -2.273,-5.753 -2.464,-5.944 cw(c-2.464,-4.717) -3.331,-5.584 -3.734,-5.182
no net on Top Layer "Top Layer-No Net 5" (solid, pour order 90): 0.66,-15.469
PGND on Top Layer "PGND_L01_P086" (solid, remove dead copper, pour order 86): 13.764,-5.713 13.894,-5.842 18.72,-5.842 18.72,-11.292 cw(c16.18,-11.292) 17.976,-13.088 10.998,-20.066 cw(c9.465,-18.533) 9.465,-20.701 0.94,-20.701 cw(c0.94,-19.72) 0.246,-20.414 -0.076,-20.091 -0.076,-18.477 cw(c2.464,-18.477) 0.668,-16.68 1.923,-15.425 cw(c3.719,-17.221) 3.719,-14.681 8.879,-14.681 ccw(c8.879,-12.141) 10.675,-13.937 11.887,-12.725 ccw(c8.913,-11.494) 11.887,-10.262 12.522,-8.007 cw(c15.062,-8.007) 13.266,-6.211
PGND on Top Layer "PGND_L01_P082" (solid, remove dead copper, pour order 82): -2.695,16.97 -3.035,16.97 ccw(c-3.036,14.432) -4.831,16.226 cw(c-5.135,16.225) -4.921,16.009 -6.337,14.719 ccw(c-5.338,12.611) -7.536,13.394 -6.976,10.033 cw(c-7.094,9.986) -7.048,9.868 cw(c-7.788,12.37) -10.312,11.709 -12.218,11.709 ccw(c-11.961,7.008) -16.662,6.752 -17.265,4.365 ccw(c-14.109,3.119) -15.317,-0.052 -14.91,-0.001 cw(c-14.808,-2.464) -12.344,-2.362 -12.344,-2.946 cw(c-14.275,-2.947) -14.275,-4.877 -18.517,-4.877 ccw(c-18.517,-5.791) -19.431,-5.791 -19.431,-12.852 ccw(c-16.891,-12.852) -16.891,-15.392 -13.919,-15.392 ccw(c-13.919,-12.852) -11.379,-12.852 -11.379,-6.528 cw(c-10.821,-6.528) -10.82,-5.969 ccw(c-10.82,-5.359) -10.211,-5.359 -10.211,-0.152 ccw(c-11.659,-0.152) -11.659,1.295 cw(c-11.659,1.803) -12.167,1.803 -12.167,3.581 ccw(c-13.132,3.581) -13.132,4.547 -13.36,4.547 cw(c-13.361,5.41) -13.767,4.648 -13.767,7.855 cw(c-13.616,7.278) -13.614,7.874 -12.065,7.874 cw(c-12.065,6.706) -10.897,6.706 ccw(c-10.643,6.706) -10.643,6.452 -4.269,6.452 ccw(c-3.608,11.603) 1.544,10.942 cw(c719.441,13.697) 1.544,16.453 ccw(c-0.61,16.427)
ISENCE on Top Layer "ISENCE_L01_P070" (solid, remove dead copper, pour order 70): -12.725,15.977 -8.618,20.084 cw(c-6.823,18.289) -6.822,20.828 7.685,20.828 cw(c7.686,18.291) 9.482,20.084 20.752,8.814 cw(c20.203,8.264) 20.98,8.262 20.98,-3.607 cw(c19.45,-3.608) 20.531,-4.691 20.269,-4.953 ccw(c20.087,-5.134) 20.085,-4.877 13.919,-4.877 cw(c13.919,-4.693) 13.789,-4.823 13.271,-4.229 ccw(c13.44,-3.823) 13.608,-4.229 13.608,-1.676 14.335,-1.458 ccw(c13.299,0.842) 15.599,-0.194 ccw(c13.431,1.232) 14.4,3.639 ccw(c-0.657,2.873) 10.254,13.277 ccw(c3.326,8.682) 3.426,16.994 ccw(c0.967,2.986) -6.969,14.789 -10.312,11.963 cw(c-10.82,15.713) -12.268,12.217 cw(c-12.062,12.954) -12.725,12.573 -12.751,15.951
MOTOR_A on Top Layer "MOTOR_A_L01_P068" (solid, remove dead copper, pour order 68): -20.46,-3.475 cw(c-18.434,-2.079) -20.853,-1.633 -20.853,6.847 cw(c-18.314,6.847) -20.109,8.643 cw(c-18.962,7.496) -18.962,9.119 -17.919,9.119 cw(c-17.535,8.153) -16.8,8.887 cw(c-17.556,8.321) -16.627,8.151 -16.913,6.584 -17.551,4.216 ccw(c-12.27,3.356) -16.612,0.229 -16.205,-0.178 ccw(c-15.96,0.068) -15.96,-0.279 -14.34,-0.279 cw(c-14.339,-1.232) -13.665,-0.559 -13.372,-0.852 cw(c-14.932,-2.412) -12.725,-2.413 cw(c-14.932,-2.413) -13.372,-3.974 -13.64,-4.242 cw(c-14.559,-3.323) -14.56,-4.623 -18.316,-4.623 cw(c-18.614,-2.603) -19.831,-4.242 -20.412,-3.57
DCIN on Top Layer "DCIN_L01_P060" (solid, remove dead copper, pour order 60): -1.186,-19.068 cw(c-3.532,-17.767) -2.794,-20.345 cw(c-2.561,-4.973) -13.596,-15.678 -13.411,-15.494 -10.469,-7.475 cw(c-10.254,-6.815) -10.744,-6.325 cw(c-10.683,-6.385) -10.683,-6.299 -10.185,-6.299 cw(c-10.499,-6.613) -10.055,-6.614 -10.055,-7.41 ccw(c-9.233,-7.41) -9.814,-7.991 -9.677,-8.128 ccw(c-9.003,-7.453) -9.003,-8.407 -1.381,-8.407 cw(c-1.637,-8.873) -1.125,-9.017 -0.94,-15.622 cw(c-2.92,-17.211) -1.125,-19.007
no net on Top Layer "Top Layer-No Net 4" (solid, pour order 58): -2.667,-19.634
no net on Top Layer "Top Layer-No Net 1" (solid, pour order 48): -11.3,-7.9
no net on Top Layer "Top Layer-No Net 2" (solid, pour order 46): -11.7,-7.9
no net on Top Layer "Top Layer-No Net 3" (solid, pour order 40): 4.2,19.8
no net on Top Layer "Top Layer-No Net" (solid, pour order 2): 3,-19.3
GND on Bottom Layer "GND_L02_P102" (solid, remove dead copper, pour order 102): -4.293,-4.648 -4.851,-4.293 cw(c-4.851,-3.759) -5.385,-3.759 -5.385,-1.143 cw(c-4.724,-1.143) -4.724,-0.483 -4.293,-0.483 ccw(c-4.293,0.076) -3.734,0.076 -3.734,1.575 cw(c-3.353,1.575) -3.353,1.956 2.515,1.956 cw(c2.515,1.295) 3.175,1.295 3.175,-0.516 ccw(c4.378,-0.516) 4.378,-1.718 7.865,-1.718 cw(c7.865,-1.981) 8.128,-1.981 8.128,-3.556 cw(c7.95,-3.556) 7.95,-3.734 4.699,-3.734 ccw(c4.699,-4.191) 4.242,-4.191 4.242,-5.105 cw(c4.191,-5.105) 4.191,-5.156 2.54,-5.156 cw(c2.54,-4.648) 2.032,-4.648 -3.937,-4.648 cw(c-4.115,-4.47)
PGND on Bottom Layer "PGND_L02_P100" (solid, remove dead copper, pour order 100): -14.741,-5.537 cw(c-14.741,-7.705) -13.208,-6.172 cw(c-14.005,-6.969) -12.878,-6.969 -12.878,-9.144 -12.174,-9.848 ccw(c-10.378,-8.052) -10.378,-10.592 -9.701,-10.592 ccw(c-9.825,-8.351) -8.146,-9.84 -4.489,-9.84 cw(c-4.489,-11.163) -3.454,-10.338 -3.454,-11.022 ccw(c-3.021,-11.022) -3.327,-11.328 ccw(c-2.53,-10.531) -2.53,-11.659 -2.21,-11.659 cw(c-2.21,-12.578) -1.559,-11.928 -1.473,-12.014 -1.473,-13.383 ccw(c0.888,-12.981) -0.497,-14.935 2.54,-14.935 cw(c2.818,-17.452) 4.402,-15.476 5.029,-16.104 5.029,-17.922 cw(c2.49,-17.922) 4.285,-19.718 4.039,-19.964 cw(c3.487,-19.413) 3.487,-20.193 -7.355,-20.193 cw(c-7.355,-17.653) -9.151,-19.449 -19.043,-9.558 cw(c-17.247,-7.762) -19.787,-7.762 -19.787,-5.639 cw(c-19.541,-5.884) -19.541,-5.537
ISENCE on Bottom Layer "ISENCE_L02_P092" (solid, remove dead copper, pour order 92): -12.7,16.002 -8.593,20.109 cw(c-6.798,18.314) -6.796,20.853 7.711,20.853 cw(c7.711,18.316) 9.507,20.109 20.777,8.839 cw(c20.228,8.289) 21.006,8.287 21.006,-3.581 cw(c19.475,-3.582) 20.557,-4.665 20.295,-4.928 ccw(c20.112,-5.109) 20.111,-4.851 13.945,-4.851 cw(c13.945,-4.667) 13.815,-4.798 13.297,-4.204 ccw(c13.465,-3.798) 13.634,-4.204 13.634,-0.721 14.166,-0.721 ccw(c14.166,1.48) 15.625,-0.168 ccw(c13.456,1.257) 14.357,3.691 ccw(c-1.007,2.909) 10.126,13.525 ccw(c3.351,8.707) 3.451,17.02 ccw(c0.992,3.011) -6.944,14.814 -10.287,11.989 cw(c-10.794,15.738) -12.243,12.243 cw(c-12.037,12.98) -12.7,12.598 -12.725,15.977
PGND on Bottom Layer "PGND_L02_P088" (solid, remove dead copper, pour order 88): 1.016,-16.891 2.355,-15.552 cw(c4.151,-17.348) 4.151,-14.808 9.204,-14.808 ccw(c9.204,-7.656) 14.261,-12.713 14.761,-12.214 cw(c15.672,-13.124) 15.672,-11.836 cw(c15.672,-12.02) 15.802,-11.89 16.129,-12.217 cw(c14.105,-12.217) 15.536,-13.648 9.38,-19.805 cw(c7.584,-18.009) 7.584,-20.549 0.546,-20.549 cw(c0.546,-20.028) 0.178,-20.396 -0.022,-20.196 cw(c0.108,-20.066) -0.076,-20.066 -0.076,-18.322 cw(c2.092,-18.322) 0.559,-16.789 ccw(c0.743,-16.605) 0.743,-16.866 0.991,-16.866
ISENCE on Bottom Layer "ISENCE_L02_P084" (solid, remove dead copper, pour order 84): -12.786,14.782 cw(c-10.056,14.571) -9.844,17.301 -6.872,17.301 cw(c-6.872,14.888) -4.459,14.888 -4.459,13.347 cw(c-8.894,12.49) -9.065,7.976 -9.415,7.976 ccw(c-9.416,7.319) -10.073,7.319 cw(c-10.377,7.319) -10.377,7.014 -12.155,7.014 cw(c-12.268,7.532) -12.786,7.42
GND on Bottom Layer "NONET_L02_P080" (solid, remove dead copper, shelved, pour order 80): -21.387,22.708 19.964,22.708 22.733,19.939 22.733,-19.812 20.041,-22.504 -20.218,-22.504 -24.333,-18.39 -24.333,19.761
DCIN on Bottom Layer "DCIN_L02_P078" (solid, remove dead copper, pour order 78): -9.971,-10.135 cw(c-9.972,-7.595) -11.768,-9.391 -12.217,-8.941 cw(c-11.666,-8.389) -12.446,-8.389 -12.446,-1.478 ccw(c-14.786,-1.478) -13.132,0.178 ccw(c-13.891,-0.58) -13.892,0.493 -15.091,0.493 -15.091,4.852 cw(c-14.733,4.852) -14.986,5.105 cw(c-14.864,4.983) -14.863,5.156 -13.132,5.156 ccw(c-13.132,6.076) -12.481,5.426 cw(c-11.466,4.41) -11.465,5.846 -9.654,5.846 -3.988,10.972 -3.988,14.438 cw(c-3.034,14.438) -3.708,15.113 cw(c-3.586,14.991) -3.586,15.164 0.086,15.164 cw(c0.086,13.778) 1.067,14.757 4.697,11.127 ccw(c5.131,11.561) 5.131,10.947 5.725,10.947 cw(c5.726,10.642) 5.943,10.857 8.842,7.958 cw(c8.646,7.958) 8.784,7.819 7.094,6.129 ccw(c8.889,4.333) 6.35,4.333 6.35,4.267 ccw(c7.637,4.267) 6.727,3.357 6.883,3.2 ccw(c8.049,4.366) 8.049,2.718 9.185,2.718 ccw(c9.246,2.779) 9.246,2.692 9.373,2.692 cw(c9.373,1.746) 10.043,2.415 13.056,-0.598 cw(c12.937,-0.718) 13.106,-0.72 13.106,-1.559 ccw(c13.89,-1.559) 13.336,-2.114 13.919,-2.658 cw(c11.483,-3.373) 13.278,-5.168 12.06,-6.386 11.501,-6.386 cw(c11.501,-3.847) 9.705,-5.642 8.249,-4.186 ccw(c7.438,-3.375) 8.585,-3.375 8.491,-2.114 ccw(c7.736,-2.426) 8.048,-1.671 7.417,-1.478 cw(c8.133,2.718) 4.301,0.864 3.124,2.134 cw(c4.342,2.941) 2.91,3.231 2.91,5.71 ccw(c0.515,6.13) 2.265,7.819 1.651,7.819 0.435,7.674 ccw(c-0.262,5.375) -1.397,7.493 -5.804,3.086 cw(c-14.886,1.238) -7.942,-4.901 ccw(c-7.246,-6.013) -8.458,-5.512 -8.458,-8.551 cw(c-10.623,-8.552) -9.093,-10.084 cw(c-9.215,-9.963) -9.216,-10.135
no net on Bottom Layer "Bottom Layer-No Net 2" (solid, pour order 72): -23.952,23.546
MOTOR_A on Bottom Layer "MOTOR_A_L02_P066" (solid, pour order 66): -14.511,14.948 -16.647,12.39 -19.83,7.831 ccw(c-18.035,6.035) -20.574,6.035 -20.574,-1.488 ccw(c-18.034,-1.488) -19.83,-3.284 -18.567,-4.547 ccw(c-18.322,-4.301) -18.322,-4.648 -13.589,-4.648 ccw(c-13.589,-4.096) -13.199,-4.487 ccw(c-14.219,-3.467) -12.776,-3.466 -12.776,-2.398 ccw(c-15.315,-2.398) -13.52,-0.602 -13.538,-0.584 ccw(c-14.58,-1.626) -14.581,-0.152 -15.545,-0.152 ccw(c-15.667,-0.152) -15.581,-0.066 cw(c-14.993,0.522) -15.824,0.522 -15.824,3.03 ccw(c-16.604,3.03) -16.053,3.581 ccw(c-16.298,3.337) -16.298,3.683 -17.323,3.683 cw(c-17.323,4.173) -17.67,3.827 -17.704,3.861 cw(c-17.519,4.045) -17.755,3.933 -17.755,4.96 cw(c-17.02,4.426) -16.993,5.334 -16.679,5.341 ccw(c-16.679,10.465) -13.056,6.842 -13.056,15.545
ISENCE on Bottom Layer "NONET_L02_P064" (solid, remove dead copper, shelved, pour order 64): -12.471,7.239 cw(c-12.448,7.641) -12.827,7.779 -12.827,15.926 cw(c-0.992,4.091) -0.992,20.828 0.314,20.828 cw(c0.315,-0.548) 14.187,15.716 cw(c-2.089,-0.562) 20.93,-0.563 20.93,-3.978 cw(c19.804,-3.979) 20.599,-4.775 cw(c19.741,-3.918) 19.741,-5.131 14.28,-5.131 cw(c14.28,-3.83) 13.36,-4.75 cw(c13.544,-4.566) 13.284,-4.566 13.284,-2.21 cw(c13.353,-2.21) 13.304,-2.161 ccw(c13.201,-2.058) 13.347,-2.058 13.347,8.435 ccw(c10.809,8.436) 12.603,10.231 7.221,15.614 ccw(c5.305,13.886) 5.288,16.466 1.815,14.707 cw(c2.449,16.848) 0.794,15.349 ccw(c-1.217,15.475) -1.017,17.48 ccw(c-0.742,13.803) -4.394,14.3 -4.394,10.134 -7.188,7.239
no net on Bottom Layer "Bottom Layer-No Net" (solid, pour order 54): -12.37,-8.788
no net on Bottom Layer "Bottom Layer-No Net 1" (solid, pour order 52): -13.208,-6.172

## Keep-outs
Keep-Out Layer:
  circle w0.127: c-0.003,-0.001 r20.75
  circle w0.127: c-5.918,-12.689 r1.5
  circle w0.127: c-8.034,11.467 r1.5
  circle w0.127: c13.944,1.221 r1.5

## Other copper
Top Layer:
  region net +5V: 3.023,-6.248 3.099,-6.325 3.099,-8.611 1.956,-8.611 1.803,-8.458 1.803,-6.655 1.499,-6.35 1.499,-6.248
  region net +5V: 1.499,-6.248
  pour cut-out: -3.413,2.864
  region net MOTOR_A: -2.235,2.921 -2.235,2.438 -5.772,2.438 -5.772,2.921
  region net MOTOR_B: -5.397,0.851 -4.191,0.851 -4.191,0.61 -4.436,0.365 -5.397,0.365
  region: -5.029,1.194
  region: -3.124,-19.812
  region: -2.972,-19.66
  pour cut-out: 14.707,-5.588
  region net PGND: -0.768,15.62 -0.768,16.97 -2.168,16.97 -2.168,15.62
  pour cut-out: -2.235,15.113 -0.33,15.113 cw(c-0.33,14.961) -0.178,14.961 -0.178,13.31 cw(c-0.483,13.31) -0.483,13.005 -2.286,13.005 cw(c-2.286,13.081) -2.362,13.081 -2.362,15.037 cw(c-2.261,15.037) -2.261,15.138
  region net +12V: -5.613,-6.629 -4.387,-6.629 cw(c-4.387,-7.41) -3.886,-6.812 -3.886,-7.879 cw(c-4.33,-7.608) -4.33,-8.128 -5.322,-8.128 cw(c-5.322,-7.608) -5.69,-7.976 -5.69,-6.777 cw(c-5.516,-6.777) -5.639,-6.655
  region net GND: 8.467,-0.711 cw(c8.467,-1.058) 8.712,-0.813 cw(c8.467,-1.058) 8.814,-1.058 8.814,-3.759 cw(c8.691,-3.637) 8.691,-3.81 8.509,-3.81 cw(c8.509,-2.532) 7.605,-3.436 7.337,-3.168 7.337,-0.831 cw(c7.424,-0.831) 7.363,-0.769 cw(c7.503,-0.909) 7.503,-0.711
  region net GND: 3.861,-2.388 3.861,-2.184 4.928,-2.184 4.928,-3.967 cw(c4.755,-3.967) 4.877,-4.089 cw(c4.693,-3.906) 4.693,-4.166 4.343,-4.166 ccw(c4.343,-4.385) 4.188,-4.23 3.737,-4.681 3.737,-5.581 2.539,-5.581 cw(c2.7,-5.192) 2.311,-5.353 2.311,-4.318 3.559,-4.318 ccw(c3.455,-4.116) 3.616,-4.277 3.886,-4.006 cw(c3.948,-3.945) 3.861,-3.945 3.861,-2.413
  region net GND: -8.763,-5.817 -6.61,-5.817 cw(c-6.61,-6.077) -6.426,-5.893 ccw(c-6.296,-5.947) -6.426,-6.001 -6.426,-8.001 cw(c-6.648,-7.985) -6.502,-8.153 -8.522,-8.153 cw(c-8.522,-7.633) -8.89,-8.001 -8.89,-6.123 cw(c-8.456,-6.123)
  region net IN: 0.66,-12.272 cw(c1.528,-12.272) 0.914,-11.659 3.499,-11.659 cw(c3.499,-11.919) 3.683,-11.735 ccw(c3.744,-11.796) 3.658,-11.796 3.658,-13.056 cw(c3.351,-12.749) 3.351,-13.183 3.327,-13.183 ccw(c3.327,-14.102) 2.677,-13.452 2.286,-13.843 ccw(c2.347,-13.904) 2.261,-13.904 2.261,-15.418 2.144,-15.534 cw(c2.057,-15.448) 2.057,-15.57 0.906,-15.57 cw(c0.906,-15.223) 0.66,-15.469
  region net MOTOR_B: 3.008,16.256 cw(c4.12,13.571) 5.232,16.256 5.349,16.256 cw(c5.349,13.717) 7.145,15.512 11.009,11.648 cw(c7.357,8.995) 11.709,7.798 ccw(c19.89,6.695) 11.709,5.593 cw(c10.41,5.593) 11.328,4.674 7.094,4.674 cw(c8.574,7.735) 5.363,6.617 5.232,7.874 ccw(c2.53,6.904) 4.191,9.246 2.35,9.997 cw(c9.695,12.572) 2.666,15.915
  pour cut-out: 11.856,1.197 ccw(c13.8,1.197) 13.8,-0.746 ccw(c13.929,1.327) 16.003,1.197 ccw(c13.8,1.197) 13.8,3.4 ccw(c13.929,1.327)
  pour cut-out: -10.144,11.297 ccw(c-8.2,11.297) -8.2,9.354 ccw(c-8.071,11.427) -5.997,11.297 ccw(c-8.2,11.297) -8.2,13.5 ccw(c-8.071,11.427)
  pour cut-out: -7.944,-12.703 ccw(c-6,-12.703) -6,-14.646 ccw(c-5.871,-12.573) -3.797,-12.703 ccw(c-6,-12.703) -6,-10.5 ccw(c-5.871,-12.573)
Bottom Layer:
  region: 0.483,1.727
  region: -2.718,-3.505
  pour cut-out: 6.858,-0.864
  region: 11.201,9.042
  region net MOTOR_A: -13.23,10.277
  region net DCIN: 9.373,2.692
  region: 9.754,2.311
  region net MOTOR_B: 9.144,8.636 10.363,8.636 10.363,6.985 9.322,6.985 9.144,7.163
  region net MOTOR_B: 7.341,15.011 6.874,15.494 10.566,11.801 10.566,8.357 10.058,7.849 9.474,7.849 6.045,11.278 4.953,11.278 3.2,13.03 3.2,14.783 4.394,15.977 6.375,15.977
  region net MOTOR_B: 7.239,5.613 9.322,7.696 10.211,7.696 11.659,6.248 11.659,4.445 11.252,4.039 8.153,4.039 7.239,4.953
  region: -12.446,-7.874
  region net DCIN: -11.913,-8.433
  region: 3.277,-7.95
  region net +5V: 2.134,-7.214 cw(c2.134,-7.442) 2.362,-7.442 2.362,-7.823 ccw(c2.532,-7.823) 2.532,-7.993 3.701,-7.993 cw(c3.701,-8.153) 3.861,-8.153 3.861,-8.534 cw(c3.734,-8.534) 3.734,-8.661 1.93,-8.661 cw(c1.93,-8.585) 1.854,-8.585 1.854,-7.366 cw(c1.949,-7.309) 1.892,-7.214
  region net IN: 3.199,-12.09 cw(c3.199,-12.524) 3.505,-12.217 cw(c3.383,-12.34) 3.556,-12.34 3.556,-12.776 cw(c3.249,-12.776) 3.466,-12.993 3.251,-13.208 cw(c2.945,-12.901) 2.945,-13.335 1.113,-13.335 cw(c1.113,-13.162) 0.991,-13.284 ccw(c0.929,-13.223) 1.016,-13.223 1.016,-12.09
  region net GND: 4.547,-12.598 5.743,-12.598 cw(c5.743,-13.205) 6.172,-12.776 ccw(c6.233,-12.837) 6.147,-12.838 6.147,-14.224 5.914,-14.457 cw(c5.618,-14.335) 5.74,-14.63 0.305,-14.63 cw(c0.393,-12.762) -0.991,-14.021 -0.991,-10.911 ccw(c-1.944,-10.911) -1.27,-10.236 ccw(c-1.637,-10.603) -1.638,-10.084 -2.6,-10.084 cw(c-2.6,-8.696) -3.581,-9.677 ccw(c-3.826,-9.922) -3.827,-9.576 -7.132,-9.576 cw(c-7.132,-8.275) -8.052,-9.195 -8.052,-5.691 cw(c-7.618,-5.691) -7.925,-5.385 -6.489,-5.385 cw(c-6.489,-5.904) -6.121,-5.537 cw(c-6.27,-5.686) -6.059,-5.687 -6.059,-7.678 ccw(c-4.884,-7.678) -5.715,-8.509 ccw(c-5.023,-7.939) -5.109,-8.832 -1.969,-8.839 ccw(c-2.071,-8.131) -1.499,-8.56 ccw(c-1.621,-8.437) -1.448,-8.437 -1.448,-7.332 ccw(c-2.522,-7.449) -2.448,-6.371 ccw(c-2.463,-6.361) -2.448,-6.352 cw(c-0.007,-3.393) -3.044,-5.736 -4.706,-4.337 cw(c-3.795,-4.05) -4.75,-4.05 -4.75,-3.988 -4.459,-3.697 cw(c-4.356,-5.22) -3.454,-3.988 -1.969,-5.473 ccw(c-1.676,-5.21) -1.638,-5.602 1.028,-5.602 cw(c0.912,-6.314) 1.499,-5.893 cw(c1.194,-6.199) 1.626,-6.199 1.626,-11.066 cw(c0.933,-11.067) 1.422,-11.557 1.147,-11.557 ccw(c1.146,-12.423) 0.533,-11.811 ccw(c1.084,-12.362) 0.305,-12.363 0.305,-13.056 ccw(c0.734,-13.056) 0.431,-13.359 0.61,-13.538 ccw(c0.978,-13.17) 0.978,-13.691 2.489,-13.691 ccw(c2.489,-11.299) 4.18,-12.99 4.547,-12.624
  region net ISENCE: 10.998,8.89 12.268,7.62 ccw(c14.131,9.255) 13.97,6.782 ccw(c13.97,7.886) 14.75,7.105 14.986,7.341 ccw(c13.944,8.383) 15.418,8.383 15.418,9.996 ccw(c13.857,9.996) 14.961,11.1 14.737,11.324 ccw(c14.015,10.378) 13.169,11.214
  region net MOTOR_C: 8.763,-13.995 ccw(c9.315,-13.443) 9.24,-14.22 ccw(c9.24,-5.9) 15.718,-11.122 ccw(c15.006,-10.804) 15.773,-10.668 11.84,-6.735 ccw(c10.044,-8.53) 10.044,-5.991 8.779,-5.991 ccw(c8.779,-6.88) 8.15,-6.252 ccw(c8.265,-6.367) 8.103,-6.367 8.103,-9.026 cw(c5.056,-9.026) 7.21,-11.181 ccw(c8.091,-11.546) 7.137,-11.546 7.137,-12.065 ccw(c7.996,-12.065) 7.389,-12.672 8.712,-13.995
  pour cut-out: 11.856,1.197 ccw(c13.8,1.197) 13.8,-0.746 ccw(c13.929,1.327) 16.003,1.197 ccw(c13.8,1.197) 13.8,3.4 ccw(c13.929,1.327)
  pour cut-out: -7.944,-12.703 ccw(c-6,-12.703) -6,-14.646 ccw(c-5.871,-12.573) -3.797,-12.703 ccw(c-6,-12.703) -6,-10.5 ccw(c-5.871,-12.573)
  pour cut-out: -10.144,11.297 ccw(c-8.2,11.297) -8.2,9.354 ccw(c-8.071,11.427) -5.997,11.297 ccw(c-8.2,11.297) -8.2,13.5 ccw(c-8.071,11.427)

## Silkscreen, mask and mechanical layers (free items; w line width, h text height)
Top Overlay:
  circle w0.127: c13.944,1.221 r3
  circle w0.127: c-8.034,11.467 r3
  circle w0.127: c-5.918,-12.689 r3
  circle w0.127: c5.414,14.113 r2.5
  circle w0.127: c-14.933,-2.366 r2.5
  circle w0.127: c9.512,-11.748 r2.5
  lines w0.12: 2.134,-3.124 2.352,-2.906 ; 2.845,-2.845 3.073,-2.845 3.073,-0.711 3.454,-0.711 5.309,-0.711 5.309,-5.659 ; 5.913,0.904 5.913,3.678 7.569,3.678 7.569,1.905 8.402,1.905 8.402,0.915 ; 8.179,-9.017 12.954,-9.017 12.954,-1.549 9.754,-1.549 8.387,-1.549 8.387,-0.737 ; 8.204,-8.992 8.204,-3.429 ; -0.559,-6.35 -0.559,-3.2 -0.508,-3.15 -0.203,-3.15 2.413,-3.15 2.413,-8.306 1.067,-8.306 1.067,-6.35 -0.559,-6.35
  lines w0.127: -19.376,4.966 ccw(c-17.439,4.47) -17.717,2.489 ccw(c-17.439,4.47) -15.501,3.973 cw(c-0.003,-0.001) -12.676,9.766 ccw(c-14.26,10.987) -12.871,12.426 ccw(c-14.26,10.987) -15.844,12.208 ccw(c-0.003,-0.001) -19.376,4.966 ; -8.124,-15.939 ccw(c-6.342,-16.847) -7.046,-18.719 ccw(c-0.003,-0.001) 6.052,-19.062 ccw(c5.446,-17.156) 7.273,-16.343 ccw(c5.446,-17.156) 4.841,-15.25 cw(c-0.003,-0.001) -5.638,-14.976 ccw(c-6.342,-16.847) -8.124,-15.939
  text "LCP037BT32EU8-V1.1" at -4.547,10.77 h0.6
  text "20220320" at 7.595,10.77 h0.6
  text "RXD" at 4.267,4.902 h0.6
  text "TXD" at 1.88,4.877 h0.6
  text "+5V" at -1.473,-8.23 h0.6 r90
  text "DIO" at -0.33,-8.255 h0.6 r90
  text "+5V" at 3.683,-8.509 h0.6 r90
  text "CLK" at -0.279,-10.465 h0.6 r90
  text "CLK" at 3.708,-10.744 h0.6 r90
  text "DIO" at 3.708,-12.903 h0.6 r90
  text "GND" at 3.81,-15.088 h0.6 r90
  text "GND" at 7.772,-15.926 h0.6
  text "V+" at -6.883,-17.882 h1.2
  text "V-" at 5.055,-18.11 h1.2
Bottom Overlay:
  lines w0.2: -11.176,-6.579 -10.135,-6.579 ; -10.744,-7.01 -10.744,-6.096 ; -0.66,12.319 0.178,12.319 ; -0.178,11.887 -0.178,12.675
  text "B" at 8.23,17.145 h1.2 r180
  text "A" at -18.7,-1.2 h1.2
  text "C" at 12.929,-12.37 h1.2 r180
  text "V+" at -5.893,-17.78 h1.2
  text "V-" at 6.909,-18.11 h1.2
